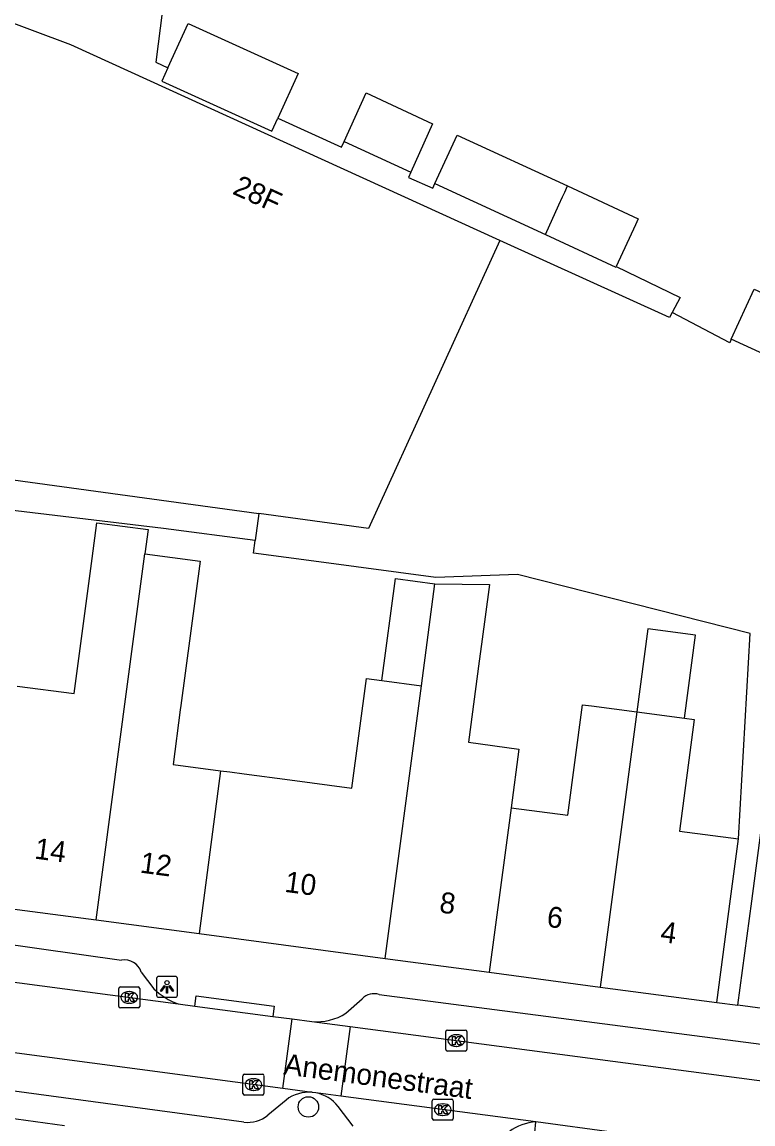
# Model space of a CAD drawing. Extents: x 161845 to 162341, y 381620 to 382158.
# Drawn here: x 162001.2 to 162036.2, y 381694.1 to 381746.8 of the extents above; entities that cross this region are included whole.
import ezdxf

# ---------------------------------------------------------------- set-up
doc = ezdxf.new("R2010")
doc.units = 0
for name, color, linetype in [('IMGEO_Boom', 7, 'Continuous'), ('IMGEO_Kolk', 7, 'Continuous'), ('IMGEO_Lichtpunt', 7, 'Continuous'), ('IMGEO_Openbare_ruimte_label', 7, 'Continuous'), ('IMGEO_Pand', 7, 'Continuous'), ('IMGEO_Pand_nummerreeks', 7, 'Continuous'), ('IMGEO_Rijbaan_lokaal_open', 7, 'Continuous'), ('IMGEO_Voetpad_open', 7, 'Continuous')]:
    doc.layers.add(name, color=color, linetype=linetype)

msp = doc.modelspace()

# ---------------------------------------------------------------- linework, layer by layer
at = {"layer": 'IMGEO_Boom'}
msp.add_circle((162014.903, 381694.955), 0.489, dxfattribs=at)
at = {"layer": 'IMGEO_Kolk'}
for p, q in [((162005.842, 381699.765), (162005.842, 381700.617)), ((162005.917, 381700.691), (162006.769, 381700.691)), ((162006.843, 381700.617), (162006.843, 381699.765)), ((162006.33, 381700.471), (162006.355, 381700.471)), ((162006.769, 381699.691), (162005.917, 381699.691)), ((162006.353, 381699.911), (162006.328, 381699.911)), ((162021.474, 381697.704), (162021.474, 381698.556)), ((162021.549, 381698.63), (162022.401, 381698.63)), ((162021.962, 381698.41), (162021.987, 381698.41)), ((162022.475, 381698.556), (162022.475, 381697.704)), ((162021.985, 381697.85), (162021.96, 381697.85)), ((162022.401, 381697.63), (162021.549, 381697.63)), ((162011.778, 381695.599), (162011.778, 381696.451)), ((162011.853, 381696.525), (162012.705, 381696.525)), ((162012.266, 381696.305), (162012.291, 381696.305)), ((162012.779, 381696.451), (162012.779, 381695.599)), ((162012.289, 381695.745), (162012.264, 381695.745)), ((162012.705, 381695.525), (162011.853, 381695.525)), ((162020.825, 381694.4), (162020.825, 381695.252)), ((162020.9, 381695.326), (162021.752, 381695.326)), ((162021.826, 381695.252), (162021.826, 381694.4)), ((162021.313, 381695.106), (162021.338, 381695.106)), ((162021.752, 381694.326), (162020.9, 381694.326)), ((162021.336, 381694.546), (162021.311, 381694.546))]:
    msp.add_line(p, q, dxfattribs=at)
for points in [[(162005.842, 381699.765), (162005.842, 381700.617)], [(162005.917, 381700.691), (162006.769, 381700.691)], [(162006.843, 381700.617), (162006.843, 381699.765)], [(162006.163, 381700.391), (162006.286, 381700.391), (162006.286, 381700.24), (162006.416, 381700.391), (162006.58, 381700.391), (162006.434, 381700.24), (162006.587, 381699.991), (162006.435, 381699.991), (162006.35, 381700.155), (162006.286, 381700.088), (162006.286, 381699.991), (162006.163, 381699.991), (162006.163, 381700.391)], [(162006.769, 381699.691), (162005.917, 381699.691)], [(162021.474, 381697.704), (162021.474, 381698.556)], [(162021.549, 381698.63), (162022.401, 381698.63)], [(162022.475, 381698.556), (162022.475, 381697.704)], [(162021.795, 381698.33), (162021.918, 381698.33), (162021.918, 381698.179), (162022.048, 381698.33), (162022.212, 381698.33), (162022.066, 381698.179), (162022.219, 381697.93), (162022.067, 381697.93), (162021.982, 381698.094), (162021.918, 381698.027), (162021.918, 381697.93), (162021.795, 381697.93), (162021.795, 381698.33)], [(162022.401, 381697.63), (162021.549, 381697.63)], [(162011.778, 381695.599), (162011.778, 381696.451)], [(162011.853, 381696.525), (162012.705, 381696.525)], [(162012.779, 381696.451), (162012.779, 381695.599)], [(162012.099, 381696.225), (162012.222, 381696.225), (162012.222, 381696.074), (162012.352, 381696.225), (162012.516, 381696.225), (162012.37, 381696.074), (162012.523, 381695.825), (162012.371, 381695.825), (162012.286, 381695.989), (162012.222, 381695.922), (162012.222, 381695.825), (162012.099, 381695.825), (162012.099, 381696.225)], [(162012.705, 381695.525), (162011.853, 381695.525)], [(162020.825, 381694.4), (162020.825, 381695.252)], [(162020.9, 381695.326), (162021.752, 381695.326)], [(162021.826, 381695.252), (162021.826, 381694.4)], [(162021.146, 381695.026), (162021.269, 381695.026), (162021.269, 381694.875), (162021.399, 381695.026), (162021.563, 381695.026), (162021.417, 381694.875), (162021.57, 381694.626), (162021.418, 381694.626), (162021.333, 381694.79), (162021.269, 381694.723), (162021.269, 381694.626), (162021.146, 381694.626), (162021.146, 381695.026)], [(162021.752, 381694.326), (162020.9, 381694.326)]]:
    msp.add_lwpolyline(points, dxfattribs=at)
for centre, start, end in [((162005.919, 381700.615), 91.552, 178.448), ((162005.919, 381700.615), 91.552, 178.448), ((162006.767, 381700.615), 1.552, 88.448), ((162006.767, 381700.615), 1.552, 88.448), ((162005.919, 381699.767), 181.552, 268.448), ((162005.919, 381699.767), 181.552, 268.448), ((162006.767, 381699.767), 271.552, 358.448), ((162006.767, 381699.767), 271.552, 358.448), ((162021.551, 381698.554), 91.552, 178.448), ((162021.551, 381698.554), 91.552, 178.448), ((162022.399, 381698.554), 1.552, 88.448), ((162022.399, 381698.554), 1.552, 88.448), ((162021.551, 381697.706), 181.552, 268.448), ((162021.551, 381697.706), 181.552, 268.448), ((162022.399, 381697.706), 271.552, 358.448), ((162022.399, 381697.706), 271.552, 358.448), ((162011.855, 381696.449), 91.552, 178.448), ((162011.855, 381696.449), 91.552, 178.448), ((162012.703, 381696.449), 1.552, 88.448), ((162012.703, 381696.449), 1.552, 88.448), ((162011.855, 381695.601), 181.552, 268.448), ((162011.855, 381695.601), 181.552, 268.448), ((162012.703, 381695.601), 271.552, 358.448), ((162012.703, 381695.601), 271.552, 358.448), ((162020.902, 381695.25), 91.552, 178.448), ((162020.902, 381695.25), 91.552, 178.448), ((162021.75, 381695.25), 1.552, 88.448), ((162021.75, 381695.25), 1.552, 88.448), ((162020.902, 381694.402), 181.552, 268.448), ((162020.902, 381694.402), 181.552, 268.448), ((162021.75, 381694.402), 271.552, 358.448), ((162021.75, 381694.402), 271.552, 358.448)]:
    msp.add_arc(centre, 0.0765, start, end, dxfattribs=at)
for centre, major_axis, ratio, start_param, end_param in [((162006.329, 381700.191), (-0.387, 0.002), 0.722429, 4.712389, 7.853982), ((162006.354, 381700.191), (-0.39, 0.002), 0.717154, 1.570796, 4.712389), ((162021.961, 381698.13), (-0.387, 0.002), 0.722429, 4.712389, 7.853982), ((162021.986, 381698.13), (-0.39, 0.002), 0.717154, 1.570796, 4.712389), ((162012.265, 381696.025), (-0.387, 0.002), 0.722429, 4.712389, 7.853982), ((162012.29, 381696.025), (-0.39, 0.002), 0.717154, 1.570796, 4.712389), ((162021.312, 381694.826), (-0.387, 0.002), 0.722429, 4.712389, 7.853982), ((162021.337, 381694.826), (-0.39, 0.002), 0.717154, 1.570796, 4.712389)]:
    msp.add_ellipse(centre, major_axis=major_axis, ratio=ratio, start_param=start_param, end_param=end_param, dxfattribs=at)
at = {"layer": 'IMGEO_Lichtpunt'}
for p, q in [((162007.65, 381701.099), (162007.65, 381700.292)), ((162007.65, 381701.099), (162007.65, 381700.292)), ((162008.552, 381701.194), (162007.744, 381701.194)), ((162008.552, 381701.194), (162007.744, 381701.194)), ((162008.646, 381700.292), (162008.646, 381701.099)), ((162008.646, 381700.292), (162008.646, 381701.099)), ((162007.744, 381700.198), (162008.552, 381700.198)), ((162007.744, 381700.198), (162008.552, 381700.198))]:
    msp.add_line(p, q, dxfattribs=at)
for points in [[(162008.024, 381700.763), (162008.063, 381700.735), (162007.875, 381700.473), (162007.837, 381700.5), (162008.024, 381700.763)], [(162008.126, 381700.715), (162008.173, 381700.715), (162008.173, 381700.393), (162008.126, 381700.393), (162008.126, 381700.715)], [(162008.236, 381700.735), (162008.274, 381700.762), (162008.461, 381700.5), (162008.422, 381700.472), (162008.236, 381700.735)]]:
    msp.add_lwpolyline(points, dxfattribs=at)
msp.add_circle((162008.149, 381700.897), 0.0994, dxfattribs=at)
for centre, start, end in [((162007.744, 381701.099), 90, 180), ((162007.744, 381701.099), 90, 180), ((162008.552, 381701.099), 0, 90), ((162008.552, 381701.099), 0, 90), ((162007.744, 381700.292), 180, 270), ((162007.744, 381700.292), 180, 270), ((162008.552, 381700.292), 270, 0), ((162008.552, 381700.292), 270, 360)]:
    msp.add_arc(centre, 0.0946, start, end, dxfattribs=at)
at = {"layer": 'IMGEO_Pand'}
for points in [[(162024.059, 381736.377), (162003.547, 381745.723), (162000, 381747.039), (161998.107, 381744.019), (161997.212, 381744.268), (161992.167, 381726.115), (162012.543, 381723.321)], [(162008.191, 381744.624), (162009.157, 381746.749), (162014.413, 381744.36), (162013.438, 381742.214)], [(162008.191, 381744.624), (162007.902, 381743.988), (162013.158, 381741.599), (162013.438, 381742.214)], [(162016.617, 381741.106), (162017.661, 381743.424), (162020.841, 381741.955), (162019.797, 381739.636)], [(162016.617, 381741.106), (162019.797, 381739.636)], [(162020.953, 381739.101), (162022.021, 381741.41), (162027.287, 381738.976)], [(162020.953, 381739.101), (162026.239, 381736.658)], [(162026.239, 381736.658), (162026.877, 381738.07), (162027.052, 381738.456), (162027.156, 381738.686), (162027.287, 381738.976)], [(162027.287, 381738.976), (162030.667, 381737.414), (162030.533, 381737.125), (162029.612, 381735.131)], [(162024.059, 381736.377), (162017.783, 381722.602), (162012.543, 381723.321)], [(162026.239, 381736.658), (162029.6, 381735.104), (162029.612, 381735.131)], [(162035.117, 381731.657), (162036.215, 381734.047), (162039.711, 381732.441), (162038.613, 381730.051)], [(162038.613, 381730.051), (162035.117, 381731.657)], [(162000.991, 381715.072), (162003.709, 381714.726), (162004.567, 381721.164), (162004.796, 381722.881), (162007.243, 381722.562), (162007.089, 381721.399)], [(162004.764, 381703.893), (162006.961, 381720.438), (162007.089, 381721.399)], [(162007.089, 381721.399), (162009.728, 381721.048), (162008.809, 381714.15), (162008.78, 381713.936), (162008.433, 381711.329), (162010.711, 381711.025)], [(162018.411, 381715.334), (162019.061, 381720.21), (162020.953, 381719.958)], [(162020.306, 381715.082), (162020.953, 381719.958)], [(162020.953, 381719.958), (162023.56, 381719.926), (162023.181, 381717.084), (162023.072, 381716.266), (162022.555, 381712.384), (162024.969, 381712.064), (162024.596, 381709.256)], [(162032.873, 381713.535), (162033.403, 381717.511), (162031.122, 381717.815), (162030.594, 381713.839)], [(162010.711, 381711.025), (162011.157, 381710.966), (162011.834, 381710.876), (162014.017, 381710.585), (162016.983, 381710.19), (162017.682, 381715.431), (162018.411, 381715.334)], [(162018.411, 381715.334), (162020.306, 381715.082)], [(162018.578, 381702.055), (162020.306, 381715.082)], [(162024.596, 381709.256), (162027.301, 381708.895), (162028.006, 381714.184), (162028.443, 381714.126), (162030.594, 381713.839)], [(162030.594, 381713.839), (162028.849, 381700.688)], [(162030.594, 381713.839), (162032.873, 381713.535)], [(162032.873, 381713.535), (162033.349, 381713.472), (162032.639, 381708.144), (162035.461, 381707.768)], [(162010.711, 381711.025), (162009.676, 381703.239)], [(162024.596, 381709.256), (162023.552, 381701.393)], [(162035.43, 381699.815), (162036.094, 381704.795), (162036.546, 381708.187)], [(162034.419, 381699.947), (162035.079, 381704.904), (162035.461, 381707.768)], [(161999.589, 381704.582), (162000, 381704.527), (162004.764, 381703.893)], [(162004.764, 381703.893), (162009.676, 381703.239)], [(162009.676, 381703.239), (162018.578, 381702.055)], [(162018.578, 381702.055), (162023.552, 381701.393)], [(162023.552, 381701.393), (162028.849, 381700.688)], [(162028.849, 381700.688), (162034.419, 381699.947)], [(162041.781, 381698.968), (162035.43, 381699.815)], [(161998.113, 381694.765), (162000, 381694.51), (162003.254, 381694.07)]]:
    msp.add_lwpolyline(points, dxfattribs=at)
at = {"layer": 'IMGEO_Rijbaan_lokaal_open'}
for points in [[(162032.292, 381732.933), (162032.161, 381732.685), (162024.059, 381736.377)], [(162035.117, 381731.657), (162035.039, 381731.487), (162032.292, 381732.933)], [(162012.543, 381723.321), (162012.365, 381722.027)], [(162035.461, 381707.768), (162036.024, 381717.58), (162024.893, 381720.414), (162020.994, 381720.268), (162015.407, 381721.012), (162012.283, 381721.428), (162012.365, 381722.027)], [(161989.215, 381702.446), (162000, 381701.025), (162008.672, 381699.882)], [(162008.672, 381699.882), (162009.479, 381699.776)], [(162009.479, 381699.776), (162013.2, 381699.286)], [(162034.419, 381699.947), (162035.43, 381699.815)], [(162013.687, 381695.839), (162000, 381697.652), (161988.767, 381699.139)], [(162013.2, 381699.286), (162014.13, 381699.163)], [(162013.687, 381695.839), (162014.13, 381699.163)], [(162014.13, 381699.163), (162015.062, 381699.04)], [(162015.062, 381699.04), (162016.905, 381698.798)], [(162016.905, 381698.798), (162016.462, 381695.471)], [(162016.905, 381698.798), (162042.617, 381695.408)], [(162015.081, 381695.654), (162013.687, 381695.839)], [(162015.262, 381695.63), (162015.081, 381695.654)], [(162016.462, 381695.471), (162015.262, 381695.63)], [(162025.782, 381694.237), (162016.462, 381695.471)], [(162029.512, 381693.742), (162025.782, 381694.237)]]:
    msp.add_lwpolyline(points, dxfattribs=at)
at = {"layer": 'IMGEO_Voetpad_open'}
for points in [[(162009.289, 381758.044), (162007.608, 381744.889), (162008.191, 381744.624)], [(162013.438, 381742.214), (162016.491, 381740.826), (162016.617, 381741.106)], [(162019.797, 381739.636), (162019.685, 381739.388), (162020.844, 381738.865), (162020.953, 381739.101)], [(162029.612, 381735.131), (162032.669, 381733.65), (162032.292, 381732.933)], [(162012.365, 381722.027), (162007.983, 381722.598), (161999.444, 381723.63)], [(161991.504, 381703.94), (162000, 381702.818), (162005.976, 381701.969)], [(162006.917, 381701.402), (162007.517, 381700.605)], [(162009.479, 381699.776), (162009.546, 381700.271), (162013.267, 381699.78), (162013.2, 381699.286)], [(162016.7, 381699.438), (162017.471, 381700.127)], [(162018.283, 381700.334), (162039.735, 381697.544)], [(162011.822, 381694.225), (162000, 381695.821), (161990.633, 381697.167)], [(162013.836, 381695.287), (162012.963, 381694.56)], [(162017.04, 381694.032), (162016.326, 381694.981)], [(162029.512, 381693.742), (162029.445, 381693.247), (162025.724, 381693.74), (162025.782, 381694.237)]]:
    msp.add_lwpolyline(points, dxfattribs=at)
for centre, radius, start, end in [((162006.119, 381701.142), 0.839, 18.0405, 99.8173), ((162009.806, 381702.977), 3.296, 226.0261, 249.8829), ((162018.053, 381699.54), 0.827, 73.8617, 134.7415), ((162015.29, 381701.673), 2.643, 265.0591, 302.2549), ((162014.927, 381693.88), 1.781, 85.0528, 127.796), ((162014.93, 381693.888), 1.773, 38.0432, 79.1935), ((162011.995, 381695.745), 1.53, 263.4937, 309.231), ((162025.923, 381691.828), 2.413, 93.3404, 126.3329)]:
    msp.add_arc(centre, radius, start, end, dxfattribs=at)

# ---------------------------------------------------------------- texts
at = {"layer": 'IMGEO_Openbare_ruimte_label'}
msp.add_text('Anemonestraat', height=1, rotation=352.4697, dxfattribs=at).set_placement((162013.687, 381696.523))
at = {"layer": 'IMGEO_Pand_nummerreeks'}
for s, rotation, p in [('28F', 335.5061, (162011.228, 381738.619)), ('14', 352.4255, (162001.78, 381706.832)), ('12', 352.4198, (162006.821, 381706.162)), ('10', 352.4198, (162013.734, 381705.242)), ('8', 352.4198, (162021.129, 381704.257)), ('6', 352.4198, (162026.26, 381703.574)), ('4', 352.4198, (162031.694, 381702.851))]:
    msp.add_text(s, height=1, rotation=rotation, dxfattribs=at).set_placement(p)

doc.saveas('drawing.dxf')
